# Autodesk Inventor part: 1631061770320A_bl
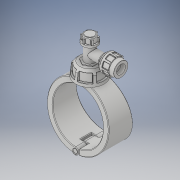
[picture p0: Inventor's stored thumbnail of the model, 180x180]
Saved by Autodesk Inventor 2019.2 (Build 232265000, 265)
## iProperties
Created: 2022-02
Part Number: 1631061770320A_bl
Material: Generic
Description: Plassadle Tapper 180x32
Document SubType Name: Modeling
Designer: comp2
Density: 1 g/cm^3
Appearance: Default
Author: comp2
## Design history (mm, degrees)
derived "16310.ipt"
feature "Solid1::16310.ipt" dims "ScaleForDerivedMember" = 10
feature "Solid2::16310.ipt" dims "ScaleForDerivedMember" = 10
feature "Solid3::16310.ipt" dims "ScaleForDerivedMember" = 10
feature "Solid4::16310.ipt" dims "ScaleForDerivedMember" = 10
tag "TaggingFeature1"
body "Solid1"
body "Solid2"
body "Solid3"
body "Solid4"
other parameters: "d7" = 209 [user parameter], "d8" = 85 deg [user parameter], "d9" = 45 deg [user parameter], "d10" = 102 [user parameter], "d11" = 49 [user parameter], "d12" = 34.3 [user parameter], "d13" = 35.7 [user parameter], "d14" = 55.08 [user parameter], "d15" = 2.45 [user parameter], "d16" = 2 [user parameter], "d17" = 2 [user parameter], "d18" = 29.4 [user parameter], "d19" = 7.35 [user parameter], "d20" = 1 [user parameter], "d21" = 30.6 [user parameter], "d22" = 1 [user parameter], "d23" = 14.7 [user parameter], "d24" = 111 [user parameter], "d27" = 144 [user parameter], "d29" = 64 [user parameter], "d31" = 51.2 [user parameter], "d32" = 44.4 [user parameter], "d33" = 15.54 [user parameter], "d34" = 93 deg [user parameter], "d35" = 2 [user parameter], "d36" = 4 [user parameter], "d39" = 45 deg [user parameter], "d40" = 4 [user parameter], "d41" = 5 [user parameter], "d42" = 4 [user parameter], "d46" = 51 [user parameter], "d47" = 32 [user parameter], "d48" = 49 [user parameter], "d49" = 4.4 [user parameter], "d51" = 0 [user parameter], "d52" = 28 [user parameter], "d53" = 121 [user parameter], "d54" = 38.5 [user parameter], "d55" = 0 [user parameter], "d56" = 22 [user parameter], "d57" = 22 [user parameter], "d59" = 0 [user parameter], "d61" = 0 [user parameter], "d62" = 38.5 [user parameter], "d63" = 0 [user parameter], "d65" = 0 [user parameter], "d67" = 0 [user parameter], "d69" = 0 [user parameter], "d70" = 1 [user parameter], "d71" = 105.6 [user parameter], "d72" = 0 [user parameter], "d73" = 2 [user parameter], "d77" = 32 [user parameter], "d78" = 86.7 [user parameter], "d79" = 5.1 [user parameter], "d80" = 60 deg [user parameter], "d81" = 5.1 [user parameter], "d84" = 0 [user parameter], "d85" = 1 [user parameter], "d87" = 360 deg [user parameter], "d90" = 0 [user parameter], "d91" = 1 [user parameter], "d93" = 60 deg [user parameter], "d94" = 3.06 [user parameter], "d95" = 3.06 [user parameter], "d97" = 0 [user parameter], "d98" = 0.5 [user parameter], "d100" = 360 deg [user parameter], "d102" = 2 [user parameter], "d105" = 0 [user parameter], "d106" = 45 deg [user parameter], "d107" = 3.2 [user parameter], "d108" = 3.2 [user parameter], "d109" = 2.95332 [user parameter], "d110" = -8 [user parameter], "d112" = 0 [user parameter], "d113" = 0.5 [user parameter], "d115" = 360 deg [user parameter], "d117" = 0.5 [user parameter], "d1" = 32 [user parameter], "E_" = 64 [user parameter], "E1" = 102 [user parameter], "H2" = 144 [user parameter], "H3" = 111 [user parameter], "H_costum" = 49 [user parameter]
